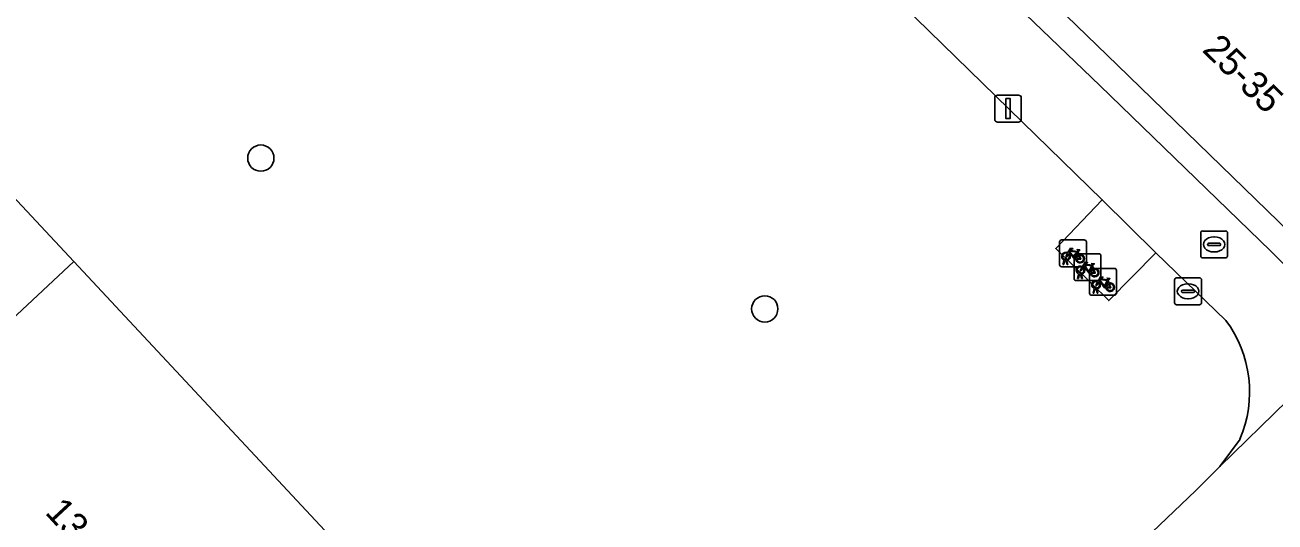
# Model space of a CAD drawing. Extents: x 162344 to 162869, y 381217 to 381818.
# Drawn here: x 162640.44 to 162687, y 381573.33 to 381591.82 of the extents above; entities that cross this region are included whole.
import ezdxf

# ---------------------------------------------------------------- set-up
doc = ezdxf.new("R2010")
doc.units = 0
for name, color, linetype in [('IMGEO_Boom', 7, 'Continuous'), ('IMGEO_Brandkraan', 7, 'Continuous'), ('IMGEO_Erf', 7, 'Continuous'), ('IMGEO_Fietsenrek', 7, 'Continuous'), ('IMGEO_Groenvoorziening', 7, 'Continuous'), ('IMGEO_Hek', 7, 'Continuous'), ('IMGEO_Kolk', 7, 'Continuous'), ('IMGEO_Lichtmast', 7, 'Continuous'), ('IMGEO_Pand', 7, 'Continuous'), ('IMGEO_Pand_nummerreeks', 7, 'Continuous'), ('IMGEO_Voetpad_open', 7, 'Continuous')]:
    doc.layers.add(name, color=color, linetype=linetype)

msp = doc.modelspace()

# ---------------------------------------------------------------- linework, layer by layer
at = {"layer": 'IMGEO_Boom'}
for centre in [(162649.226, 381586.87), (162667.996, 381581.258)]:
    msp.add_circle(centre, 0.489, dxfattribs=at)
at = {"layer": 'IMGEO_Brandkraan'}
for p, q in [((162684.307, 381584.157), (162685.159, 381584.157)), ((162684.232, 381583.231), (162684.232, 381584.083)), ((162684.534, 381583.7), (162684.932, 381583.7)), ((162684.72, 381583.937), (162684.745, 381583.937)), ((162685.233, 381584.083), (162685.233, 381583.231)), ((162684.491, 381583.651), (162684.491, 381583.663)), ((162684.929, 381583.614), (162684.531, 381583.614)), ((162684.743, 381583.377), (162684.718, 381583.377)), ((162684.975, 381583.663), (162684.975, 381583.651)), ((162685.159, 381583.157), (162684.307, 381583.157))]:
    msp.add_line(p, q, dxfattribs=at)
for points in [[(162684.307, 381584.157), (162685.159, 381584.157)], [(162684.232, 381583.231), (162684.232, 381584.083)], [(162685.233, 381584.083), (162685.233, 381583.231)], [(162685.159, 381583.157), (162684.307, 381583.157)]]:
    msp.add_lwpolyline(points, dxfattribs=at)
for centre, radius, start, end in [((162684.309, 381584.081), 0.0765, 91.552, 178.448), ((162684.309, 381584.081), 0.0765, 91.552, 178.448), ((162685.157, 381584.081), 0.0765, 1.552, 88.448), ((162685.157, 381584.081), 0.0765, 1.552, 88.448), ((162684.531, 381583.66), 0.0403, 85.8775, 175.7526), ((162684.936, 381583.662), 0.0386, 1.7309, 96.639), ((162684.309, 381583.233), 0.0765, 181.552, 268.448), ((162684.309, 381583.233), 0.0765, 181.552, 268.448), ((162684.528, 381583.65), 0.0366, 178.938, 274.7102), ((162684.932, 381583.657), 0.043, 264.8664, 352.4533), ((162685.157, 381583.233), 0.0765, 271.552, 358.448), ((162685.157, 381583.233), 0.0765, 271.552, 358.448)]:
    msp.add_arc(centre, radius, start, end, dxfattribs=at)
for centre, major_axis, ratio, start_param, end_param in [((162684.719, 381583.657), (-0.387, 0.002), 0.722429, 4.712389, 7.853982), ((162684.744, 381583.657), (-0.39, 0.002), 0.717154, 1.570796, 4.712389)]:
    msp.add_ellipse(centre, major_axis=major_axis, ratio=ratio, start_param=start_param, end_param=end_param, dxfattribs=at)
at = {"layer": 'IMGEO_Erf'}
msp.add_lwpolyline([(162668.681, 381602.417), (162665.532, 381605.474), (162662.563, 381608.357), (162656.251, 381614.485), (162652.976, 381617.664), (162652.285, 381616.955), (162655.527, 381613.812), (162661.834, 381607.667), (162667.976, 381601.726), (162674.343, 381595.464), (162680.473, 381589.574), (162686.832, 381583.418), (162689.987, 381580.301), (162690.713, 381581.029), (162687.566, 381584.084), (162681.138, 381590.324), (162678.089, 381593.285), (162675.103, 381596.183)], close=True, dxfattribs=at)
at = {"layer": 'IMGEO_Fietsenrek'}
for p, q in [((162678.975, 381582.901), (162678.975, 381583.742)), ((162678.975, 381583.742), (162678.975, 381582.901)), ((162679.05, 381583.826), (162679.891, 381583.826)), ((162679.891, 381583.826), (162679.05, 381583.826)), ((162679.975, 381583.751), (162679.975, 381582.91)), ((162679.975, 381582.91), (162679.975, 381583.751)), ((162679.516, 381582.386), (162679.516, 381583.227)), ((162679.516, 381583.227), (162679.516, 381582.386)), ((162679.591, 381583.311), (162680.432, 381583.311)), ((162680.432, 381583.311), (162679.591, 381583.311)), ((162679.662, 381583.375), (162679.698, 381583.28)), ((162680.516, 381583.236), (162680.516, 381582.395)), ((162680.516, 381582.395), (162680.516, 381583.236)), ((162679.9, 381582.826), (162679.059, 381582.826)), ((162679.059, 381582.826), (162679.9, 381582.826)), ((162679.102, 381582.91), (162679.141, 381583.07)), ((162679.136, 381582.91), (162679.102, 381582.91)), ((162679.171, 381583.058), (162679.136, 381582.91)), ((162679.213, 381583.082), (162679.212, 381583.086)), ((162679.254, 381582.91), (162679.22, 381583.052)), ((162679.244, 381583.093), (162679.245, 381583.086)), ((162679.252, 381583.056), (162679.287, 381582.91)), ((162679.287, 381582.91), (162679.254, 381582.91)), ((162680.169, 381582.765), (162681.01, 381582.765)), ((162681.01, 381582.765), (162680.169, 381582.765)), ((162680.203, 381582.86), (162680.239, 381582.765)), ((162680.441, 381582.311), (162679.6, 381582.311)), ((162679.6, 381582.311), (162680.441, 381582.311)), ((162679.643, 381582.395), (162679.682, 381582.555)), ((162679.677, 381582.395), (162679.643, 381582.395)), ((162679.712, 381582.543), (162679.677, 381582.395)), ((162679.754, 381582.567), (162679.753, 381582.571)), ((162679.795, 381582.395), (162679.761, 381582.537)), ((162679.785, 381582.578), (162679.786, 381582.571)), ((162679.793, 381582.541), (162679.828, 381582.395)), ((162679.828, 381582.395), (162679.795, 381582.395)), ((162680.094, 381581.84), (162680.094, 381582.681)), ((162680.094, 381582.681), (162680.094, 381581.84)), ((162680.781, 381582.314), (162680.817, 381582.219)), ((162681.094, 381582.69), (162681.094, 381581.849)), ((162681.094, 381581.849), (162681.094, 381582.69)), ((162680.221, 381581.849), (162680.26, 381582.009)), ((162680.255, 381581.849), (162680.221, 381581.849)), ((162680.29, 381581.997), (162680.255, 381581.849)), ((162680.332, 381582.021), (162680.331, 381582.025)), ((162680.373, 381581.849), (162680.339, 381581.991)), ((162680.363, 381582.032), (162680.364, 381582.025)), ((162680.371, 381581.995), (162680.406, 381581.849)), ((162680.406, 381581.849), (162680.373, 381581.849)), ((162681.019, 381581.765), (162680.178, 381581.765)), ((162680.178, 381581.765), (162681.019, 381581.765))]:
    msp.add_line(p, q, dxfattribs=at)
for points in [[(162679.309, 381583.3), (162679.257, 381583.21), (162679.217, 381583.185), (162679.218, 381583.232), (162679.273, 381583.326)], [(162679.288, 381583.352), (162679.383, 381583.516), (162679.469, 381583.502), (162679.471, 381583.493), (162679.415, 381583.482), (162679.388, 381583.437), (162679.644, 381583.396)], [(162679.584, 381583.108), (162679.534, 381583.108), (162679.343, 381583.359), (162679.324, 381583.327)], [(162679.631, 381583.371), (162679.374, 381583.412), (162679.357, 381583.383), (162679.524, 381583.163), (162679.631, 381583.371)], [(162679.679, 381583.273), (162679.649, 381583.35), (162679.54, 381583.132), (162679.583, 381583.132)], [(162679.613, 381583.132), (162679.733, 381583.131), (162679.689, 381583.245)], [(162679.709, 381583.252), (162679.764, 381583.107), (162679.614, 381583.107)], [(162679.644, 381583.396), (162679.669, 381583.445), (162679.663, 381583.449), (162679.64, 381583.453), (162679.628, 381583.46), (162679.627, 381583.463), (162679.629, 381583.468), (162679.724, 381583.453), (162679.726, 381583.443), (162679.716, 381583.43), (162679.704, 381583.424), (162679.69, 381583.43), (162679.662, 381583.375)], [(162679.85, 381582.785), (162679.798, 381582.695), (162679.758, 381582.67), (162679.759, 381582.717), (162679.814, 381582.811)], [(162679.829, 381582.837), (162679.924, 381583.001), (162680.01, 381582.987), (162680.012, 381582.978), (162679.956, 381582.967), (162679.929, 381582.922), (162680.185, 381582.881)], [(162680.125, 381582.593), (162680.075, 381582.593), (162679.884, 381582.844), (162679.865, 381582.812)], [(162680.172, 381582.856), (162679.915, 381582.897), (162679.898, 381582.868), (162680.065, 381582.648), (162680.172, 381582.856)], [(162680.22, 381582.758), (162680.19, 381582.835), (162680.081, 381582.617), (162680.124, 381582.617)], [(162680.185, 381582.881), (162680.21, 381582.93), (162680.204, 381582.934), (162680.181, 381582.938), (162680.169, 381582.945), (162680.168, 381582.948), (162680.17, 381582.953), (162680.265, 381582.938), (162680.267, 381582.928), (162680.257, 381582.915), (162680.245, 381582.909), (162680.231, 381582.915), (162680.203, 381582.86)], [(162680.154, 381582.617), (162680.274, 381582.616), (162680.23, 381582.73)], [(162680.25, 381582.737), (162680.305, 381582.592), (162680.155, 381582.592)], [(162680.407, 381582.291), (162680.502, 381582.455), (162680.588, 381582.441), (162680.59, 381582.432), (162680.534, 381582.421), (162680.507, 381582.376), (162680.763, 381582.335)], [(162680.703, 381582.047), (162680.653, 381582.047), (162680.462, 381582.298), (162680.443, 381582.266)], [(162680.75, 381582.31), (162680.493, 381582.351), (162680.476, 381582.322), (162680.643, 381582.102), (162680.75, 381582.31)], [(162680.763, 381582.335), (162680.788, 381582.384), (162680.782, 381582.388), (162680.759, 381582.392), (162680.747, 381582.399), (162680.746, 381582.402), (162680.748, 381582.407), (162680.843, 381582.392), (162680.845, 381582.382), (162680.835, 381582.369), (162680.823, 381582.363), (162680.809, 381582.369), (162680.781, 381582.314)], [(162680.428, 381582.239), (162680.376, 381582.149), (162680.336, 381582.124), (162680.337, 381582.171), (162680.392, 381582.265)], [(162680.798, 381582.212), (162680.768, 381582.289), (162680.659, 381582.071), (162680.702, 381582.071)], [(162680.732, 381582.071), (162680.852, 381582.07), (162680.808, 381582.184)], [(162680.828, 381582.191), (162680.883, 381582.046), (162680.733, 381582.046)]]:
    msp.add_lwpolyline(points, dxfattribs=at)
for centre, radius, start, end in [((162679.053, 381583.748), 0.0779, 92.4484, 184.2845), ((162679.053, 381583.748), 0.0779, 92.4484, 184.2845), ((162679.897, 381583.748), 0.0779, 2.4484, 94.2845), ((162679.897, 381583.748), 0.0779, 2.4484, 94.2845), ((162679.215, 381583.211), 0.159, 62.6766, 242.1369), ((162679.215, 381583.211), 0.129, 63.3192, 238.903), ((162679.215, 381583.211), 0.129, 283.6043, 43.4302), ((162679.215, 381583.211), 0.159, 283.5766, 46.6042), ((162679.594, 381583.233), 0.0779, 92.4484, 184.2845), ((162679.594, 381583.233), 0.0779, 92.4484, 184.2845), ((162679.742, 381583.127), 0.159, 113.3408, 178.3217), ((162679.742, 381583.127), 0.159, 187.0065, 105.7708), ((162679.742, 381583.127), 0.129, 113.923, 177.9556), ((162679.742, 381583.127), 0.129, 188.6715, 104.5883), ((162680.438, 381583.233), 0.0779, 2.4484, 94.2845), ((162680.438, 381583.233), 0.0779, 2.4484, 94.2845), ((162679.053, 381582.904), 0.0779, 182.4484, 274.2845), ((162679.053, 381582.904), 0.0779, 182.4484, 274.2845), ((162679.195, 381583.082), 0.0499, 12.8025, 158.6934), ((162679.215, 381583.211), 0.159, 253.9967, 271.7867), ((162679.195, 381583.082), 0.0174, 12.8025, 163.4502), ((162679.215, 381583.211), 0.129, 253.415, 269.0204), ((162679.756, 381582.696), 0.159, 62.6766, 242.1369), ((162679.756, 381582.696), 0.129, 63.3192, 238.903), ((162679.756, 381582.696), 0.129, 283.6043, 43.4302), ((162679.756, 381582.696), 0.159, 283.5766, 46.6042), ((162679.897, 381582.904), 0.0779, 272.4484, 4.2845), ((162679.897, 381582.904), 0.0779, 272.4484, 4.2845), ((162680.172, 381582.687), 0.0779, 92.4484, 184.2845), ((162680.172, 381582.687), 0.0779, 92.4484, 184.2845), ((162680.283, 381582.612), 0.159, 187.0065, 105.7708), ((162681.016, 381582.687), 0.0779, 2.4484, 94.2845), ((162681.016, 381582.687), 0.0779, 2.4484, 94.2845), ((162679.594, 381582.389), 0.0779, 182.4484, 274.2845), ((162679.594, 381582.389), 0.0779, 182.4484, 274.2845), ((162679.736, 381582.567), 0.0499, 12.8025, 158.6934), ((162679.756, 381582.696), 0.159, 253.9967, 271.7867), ((162679.736, 381582.567), 0.0174, 12.8025, 163.4502), ((162679.756, 381582.696), 0.129, 253.415, 269.0204), ((162680.283, 381582.612), 0.159, 113.3408, 178.3217), ((162680.283, 381582.612), 0.129, 113.923, 177.9556), ((162680.283, 381582.612), 0.129, 188.6715, 104.5883), ((162680.334, 381582.15), 0.159, 62.6766, 242.1369), ((162680.438, 381582.389), 0.0779, 272.4484, 4.2845), ((162680.438, 381582.389), 0.0779, 272.4484, 4.2845), ((162680.172, 381581.843), 0.0779, 182.4484, 274.2845), ((162680.172, 381581.843), 0.0779, 182.4484, 274.2845), ((162680.334, 381582.15), 0.129, 63.3192, 238.903), ((162680.314, 381582.021), 0.0499, 12.8025, 158.6934), ((162680.334, 381582.15), 0.159, 253.9967, 271.7867), ((162680.314, 381582.021), 0.0174, 12.8025, 163.4502), ((162680.334, 381582.15), 0.129, 253.415, 269.0204), ((162680.334, 381582.15), 0.129, 283.6043, 43.4302), ((162680.334, 381582.15), 0.159, 283.5766, 46.6042), ((162680.861, 381582.066), 0.159, 113.3408, 178.3217), ((162680.861, 381582.066), 0.159, 187.0065, 105.7708), ((162680.861, 381582.066), 0.129, 113.923, 177.9556), ((162680.861, 381582.066), 0.129, 188.6715, 104.5883), ((162681.016, 381581.843), 0.0779, 272.4484, 4.2845), ((162681.016, 381581.843), 0.0779, 272.4484, 4.2845)]:
    msp.add_arc(centre, radius, start, end, dxfattribs=at)
at = {"layer": 'IMGEO_Groenvoorziening'}
for points in [[(162685.167, 381580.827), (162682.562, 381583.343), (162680.805, 381581.569), (162678.833, 381583.511), (162680.565, 381585.323), (162670.159, 381595.461), (162668.394, 381593.687), (162666.339, 381595.619), (162668.158, 381597.447), (162656.566, 381608.626), (162654.824, 381606.815), (162652.827, 381608.774), (162654.594, 381610.607), (162652.937, 381612.199)], [(162647.237, 381612.021), (162630.312, 381595.808), (162630.497, 381595.61), (162642.256, 381583.018), (162654.2, 381570.228), (162666.036, 381557.553), (162666.149, 381557.432), (162684.056, 381574.498), (162684.949, 381575.398), (162685.696, 381576.414)]]:
    msp.add_lwpolyline(points, dxfattribs=at)
msp.add_arc((162681.611, 381578.163), 4.443, 336.8248, 36.8464, dxfattribs=at)
at = {"layer": 'IMGEO_Hek'}
msp.add_lwpolyline([(162684.056, 381574.498), (162666.149, 381557.432)], dxfattribs=at)
at = {"layer": 'IMGEO_Kolk'}
for p, q in [((162683.261, 381581.488), (162683.261, 381582.34)), ((162683.336, 381582.414), (162684.188, 381582.414)), ((162684.262, 381582.34), (162684.262, 381581.488)), ((162683.52, 381581.908), (162683.52, 381581.92)), ((162683.958, 381581.871), (162683.56, 381581.871)), ((162683.563, 381581.957), (162683.961, 381581.957)), ((162683.749, 381582.194), (162683.774, 381582.194)), ((162684.004, 381581.92), (162684.004, 381581.908)), ((162684.188, 381581.414), (162683.336, 381581.414)), ((162683.772, 381581.634), (162683.747, 381581.634))]:
    msp.add_line(p, q, dxfattribs=at)
for points in [[(162683.261, 381581.488), (162683.261, 381582.34)], [(162683.336, 381582.414), (162684.188, 381582.414)], [(162684.262, 381582.34), (162684.262, 381581.488)], [(162684.188, 381581.414), (162683.336, 381581.414)]]:
    msp.add_lwpolyline(points, dxfattribs=at)
for centre, radius, start, end in [((162683.338, 381582.338), 0.0765, 91.552, 178.448), ((162683.338, 381582.338), 0.0765, 91.552, 178.448), ((162684.186, 381582.338), 0.0765, 1.552, 88.448), ((162684.186, 381582.338), 0.0765, 1.552, 88.448), ((162683.56, 381581.917), 0.0403, 85.8775, 175.7526), ((162683.557, 381581.907), 0.0366, 178.938, 274.7102), ((162683.961, 381581.914), 0.043, 264.8664, 352.4533), ((162683.965, 381581.919), 0.0386, 1.7309, 96.639), ((162683.338, 381581.49), 0.0765, 181.552, 268.448), ((162683.338, 381581.49), 0.0765, 181.552, 268.448), ((162684.186, 381581.49), 0.0765, 271.552, 358.448), ((162684.186, 381581.49), 0.0765, 271.552, 358.448)]:
    msp.add_arc(centre, radius, start, end, dxfattribs=at)
for centre, major_axis, ratio, start_param, end_param in [((162683.748, 381581.914), (-0.387, 0.002), 0.722429, 4.712389, 7.853982), ((162683.773, 381581.914), (-0.39, 0.002), 0.717154, 1.570796, 4.712389)]:
    msp.add_ellipse(centre, major_axis=major_axis, ratio=ratio, start_param=start_param, end_param=end_param, dxfattribs=at)
at = {"layer": 'IMGEO_Lichtmast'}
for p, q in [((162676.56, 381588.314), (162676.56, 381589.114)), ((162676.56, 381589.114), (162676.56, 381588.314)), ((162676.66, 381589.214), (162677.45, 381589.214)), ((162677.45, 381589.214), (162676.66, 381589.214)), ((162677.55, 381589.114), (162677.55, 381588.314)), ((162677.55, 381588.314), (162677.55, 381589.114)), ((162677.45, 381588.214), (162676.66, 381588.214)), ((162676.66, 381588.214), (162677.45, 381588.214))]:
    msp.add_line(p, q, dxfattribs=at)
msp.add_lwpolyline([(162676.98, 381589.089), (162677.13, 381589.089), (162677.13, 381588.339), (162676.98, 381588.339), (162676.98, 381589.089)], dxfattribs=at)
for centre, start, end in [((162676.66, 381589.114), 90, 180), ((162676.66, 381589.114), 90, 180), ((162677.45, 381589.114), 0, 90), ((162677.45, 381589.114), 360, 90), ((162676.66, 381588.314), 180, 270), ((162676.66, 381588.314), 180, 270), ((162677.45, 381588.314), 270, 0), ((162677.45, 381588.314), 270, 0)]:
    msp.add_arc(centre, 0.1, start, end, dxfattribs=at)
at = {"layer": 'IMGEO_Pand'}
for points in [[(162678.089, 381593.285), (162681.138, 381590.324), (162687.566, 381584.084), (162690.713, 381581.029), (162694.297, 381584.72), (162697.423, 381587.94), (162684.799, 381600.196)], [(162635.123, 381576.357), (162642.256, 381583.018), (162630.497, 381595.61), (162630.312, 381595.808), (162623.179, 381589.147), (162626.135, 381585.982), (162632.154, 381579.537)], [(162654.2, 381570.228), (162642.256, 381583.018), (162635.123, 381576.357), (162637.954, 381573.325), (162644.391, 381566.431), (162647.067, 381563.566)]]:
    msp.add_lwpolyline(points, close=True, dxfattribs=at)
at = {"layer": 'IMGEO_Voetpad_open'}
for points in [[(162652.937, 381612.199), (162654.594, 381610.607), (162656.566, 381608.626), (162668.158, 381597.447), (162670.159, 381595.461), (162680.565, 381585.323), (162682.562, 381583.343), (162685.167, 381580.827)], [(162685.696, 381576.414), (162684.949, 381575.398), (162689.987, 381580.301), (162686.832, 381583.418), (162680.473, 381589.574), (162674.343, 381595.464), (162667.976, 381601.726), (162661.834, 381607.667)], [(162652.789, 381539.978), (162658.834, 381545.613), (162660.899, 381547.426), (162661.644, 381548.08), (162663.871, 381550.035), (162680.903, 381566.354), (162690.864, 381575.813), (162691.765, 381574.889), (162694.262, 381577.583), (162690.713, 381581.029), (162689.987, 381580.301), (162684.949, 381575.398), (162684.056, 381574.498), (162666.149, 381557.432), (162666.382, 381557.182), (162659.249, 381550.521), (162658.64, 381550.091), (162653.565, 381545.59), (162636.284, 381529.266)]]:
    msp.add_lwpolyline(points, dxfattribs=at)
msp.add_lwpolyline([(162680.565, 381585.323), (162678.833, 381583.511), (162680.805, 381581.569), (162682.562, 381583.343)], close=True, dxfattribs=at)
msp.add_arc((162681.611, 381578.163), 4.443, 336.8248, 36.8464, dxfattribs=at)

# ---------------------------------------------------------------- texts
at = {"layer": 'IMGEO_Pand_nummerreeks'}
for s, rotation, p in [('25-35', 315.5695, (162684.254, 381590.864)), ('13-23', 312.8195, (162641.155, 381573.661))]:
    msp.add_text(s, height=1, rotation=rotation, dxfattribs=at).set_placement(p)

doc.saveas('drawing.dxf')
